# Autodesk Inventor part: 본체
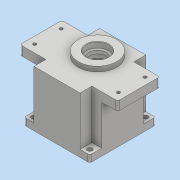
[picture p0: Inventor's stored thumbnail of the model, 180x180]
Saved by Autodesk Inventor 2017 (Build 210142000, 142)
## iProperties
Part Number: 본체
Material: 일반
Document SubType Name: Modeling
Designer: user
Density: 1 g/cm^3
Appearance: 기본값
Mass: 324.574 g
Surface Area: 793.93 cm^2
Volume: 324.574 cm^3
Author: user
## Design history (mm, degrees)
sketch "스케치1"
  geometry: L1 (0, 60)-(140, 60); L2 (140, 60)-(140, 0); L3 (140, 0)-(0, 0); L4 (0, 0)-(0, 60); L5 (37, 77)-(103, 77); L6 (103, 77)-(103, -17); L7 (103, -17)-(37, -17); L8 (37, -17)-(37, 77); 1 further point
  constraints: 16 end point, 4 parallel, 2 horizontal, 2 perpendicular, 2 point on line
  dimensions: "d0" = 140 distance of L2.end L3.end; "d1" = 60 distance of L1.end L2.end; "d2" = 66 distance of L6.end L7.end; "d3" = 94 distance of L5.end L6.end; "d4" = 17 distance between parallel lines of L1 L5; "d5" = 37 distance between parallel lines of L4 L8
extrude "돌출1" new body sketch "스케치1" distance "d6" = 13; taper "d7" = 0 deg
sketch "스케치3"
  geometry: L1 (-37, 77)-(-103, 77) reference; L2 (-37, -17)-(-103, -17); L3 (-103, -17)-(-103, 77); L4 (-103, 77)-(-37, 77); L5 (-37, 77)-(-37, -17); L6 (-37, 0)-(0, 0) reference; L7 (-23, 0)-(-117, 0); L8 (-117, 0)-(-117, 60); L9 (-117, 60)-(-23, 60); L10 (-23, 60)-(-23, 0)
  constraints: 16 end point, 4 parallel, 2 horizontal, 2 perpendicular, 1 point on line
  dimensions: "d8" = 94 distance of L8.end L9.end; "d9" = 60 distance of L7.end L8.end; "d10" = 14 distance between parallel lines of L10 L5
extrude "돌출2" join sketch "스케치3" distance "d11" = 57; taper "d12" = 0 deg
sketch "스케치4"
  geometry: L1 (-23, -17)-(-117, -17); L2 (-117, -17)-(-117, 77); L3 (-117, 77)-(-23, 77); L4 (-23, 77)-(-23, -17); 3 further points
  constraints: 8 end point, 2 parallel, 2 point on line, 1 horizontal, 1 perpendicular
  dimensions: "d13" = 94 distance of L2.end L3.end; "d14" = 94 distance of L1.end L2.end
extrude "돌출3" join sketch "스케치4" distance "d15" = 10; taper "d16" = 0 deg
sketch "스케치5"
  geometry: L1 (37, -17)-(103, -17) reference; L2 (103, 77)-(37, 77) reference; C1 r 27.5 at (70, 41); 2 further points
  constraints: 1 centre point, 1 midpoint, 1 vertical alignment
  dimensions: "d17" = 55 diameter of C1; "d18" = 58 distance from line of L1 C1.centre
extrude "돌출4" join sketch "스케치5" distance "d19" = 7; taper "d20" = 0 deg
sketch "스케치6"
  geometry: C1 r 16 at (0, 0); C2 r 27.5 at (0, 0) reference; 1 further point
  constraints: 1 centre point, 1 concentric
  dimensions: "d21" = 32 diameter of C1
extrude "돌출5" cut sketch "스케치6" distance "d22" = 8.3; taper "d23" = 0 deg
sketch "스케치7"
  geometry: C1 r 12.5 at (0, 0); C2 r 16 at (0, 0) reference; 1 further point
  constraints: 1 centre point, 1 concentric
  dimensions: "d24" = 25 diameter of C1
extrude "돌출6" cut sketch "스케치7" distance "d25" = 4.7; taper "d26" = 0 deg
sketch "스케치8"
  geometry: C1 r 17.5 at (0, 0); C2 r 12.5 at (0, 0) reference; 1 further point
  constraints: 1 centre point, 1 concentric
  dimensions: "d27" = 35 diameter of C1
sketch "스케치9"
  geometry: L1 (0, 0)-(0, 60) reference; L2 (-23, 77)-(-117, 77) reference; C1 r 43 at (-70, 30)
  constraints: 1 centre point
  dimensions: "d28" = 86 diameter of C1; "d29" = 70 distance from line of L1 C1.centre; "d30" = 47 distance from line of C1.centre L2
extrude "돌출7" cut sketch "스케치9" distance "d31" = 9; taper "d32" = 0 deg
sketch "스케치10"
  geometry: C1 r 40 at (0, 0); C2 r 43 at (0, 0) reference; 1 further point
  constraints: 1 centre point, 1 concentric
  dimensions: "d33" = 80 diameter of C1
extrude "돌출8" cut sketch "스케치10" distance "d34" = 62; taper "d35" = 0 deg
sketch "스케치11"
  geometry: C1 r 40 at (0, 0) reference; C2 r 21 at (0, 11); C3 r 15 at (0, -20); 1 further point
  constraints: 2 centre point, 2 vertical alignment
  dimensions: "d36" = 42 diameter of C2; "d37" = 30 diameter of C3; "d38" = 11 distance of C1.centre C2.centre; "d39" = 20 distance of C3.centre C1.centre
extrude "돌출9" join sketch "스케치11" distance "d40" = 7; taper "d41" = 0 deg
extrude "돌출10" cut sketch "스케치8" distance "d42" = 57; taper "d43" = 0 deg
sketch "스케치12"
  geometry: C1 r 11 at (0, -20); A1 r 15 centre (0, -20) between (-8.978, -7.984) and (8.978, -7.984) reference; 1 further point
  constraints: 1 centre point, 1 concentric
  dimensions: "d44" = 22 diameter of C1
extrude "돌출11" cut sketch "스케치12" distance "d45" = 7; taper "d46" = 0 deg
sketch "스케치13"
  geometry: C1 r 9.5 at (0, 0); C2 r 11 at (0, 0) reference; 1 further point
  constraints: 1 centre point, 1 concentric
  dimensions: "d47" = 19 diameter of C1
extrude "돌출12" cut sketch "스케치13" distance "d48" = 3; taper "d49" = 0 deg
sketch "스케치14"
  geometry: L1 (103, 77)-(37, 77) reference; L2 (23, 77)-(23, 60) reference; 2 further points
  dimensions: "d50" = 7 distance from line of L1 point (30, 70); "d51" = 7 distance from line of L2 point (30, 70)
hole "구멍1" sketch "스케치14" at (30, 70) diameter "d52" = 7; stored, may be unused: countersink angle "d56" = 90 deg, drill point angle "d58" = 118 deg; dims "d53" = 6, "d54" = 4, "d55" = 2, "d57" = 8
sketch "스케치17"
  geometry: L1 (0, 60)-(-23, 60) reference; L2 (0, 0)-(0, 60) reference; 1 further point
  dimensions: "d65" = 49 distance from line of L1 point (-10, 11); "d66" = 10 distance from line of L2 point (-10, 11)
hole "구멍2" sketch "스케치17" at (-10, 11) diameter "d67" = 4.5; stored, may be unused: countersink angle "d71" = 90 deg, drill point angle "d73" = 118 deg; dims "d68" = 6, "d69" = 10, "d70" = 5, "d72" = 8
sketch "스케치20"
  geometry: A1 r 40 centre (0, 0) between (39.279, 7.559) and (39.279, -7.559) reference; A2 r 4 centre (36, 0) between (36.19, 3.995) and (36.19, -3.995); A3 r 3 centre (36.333, 6.992) between (36.19, 3.995) and (39.279, 7.559); A4 r 3 centre (36.333, -6.992) between (39.279, -7.559) and (36.19, -3.995); 1 further point
  constraints: 8 point on circle, 4 tangent, 3 centre point, 1 horizontal alignment
  dimensions: "d86" = 8 diameter of A2; "d87" = 36 distance of A1.centre A2.centre; "d88" = 3 radius of A3; "d89" = 3 radius of A4
extrude "돌출13" join sketch "스케치20" stored distance "d90" = 3; taper "d91" = 0 deg
hole "구멍3" diameter "d94" = 3.242; stored, may be unused: countersink angle "d98" = 90 deg, drill point angle "d100" = 118 deg; dims "d92" = 10, "d93" = 10, "d95" = 7, "d96" = 10, "d97" = 5, "d99" = 9
node "작업 평면1"
sketch "스케치21"
  geometry: L1 (-14, 80)-(80, 80) reference; L2 (66, 0)-(66, 70) reference; 2 further points
  constraints: 1 other
  dimensions: "d102" = 40 distance from line of L1 point (33, 40); "d103" = 33 distance from line of L2 point (33, 40)
feature "엠보싱1" sketch "스케치21" dims "d8" = 94, "d9" = 60, "d10" = 14, "d104" = 0.5, "d105" = 0
fillet "모깎기1" dims "d106" = 3
fillet "모깎기2" dims "d107" = 3
chamfer "모따기1" distance "d108" = 1; stored, may be unused: second distance "d109" = 2, angle "d110" = 45 deg
chamfer "모따기2" distance "d111" = 0.8; stored, may be unused: second distance "d112" = 2, angle "d113" = 30 deg
fillet "모깎기3" dims "d114" = 3
chamfer "모따기3" distance "d115" = 1; stored, may be unused: second distance "d116" = 2, angle "d117" = 30 deg
chamfer "모따기4" distance "d118" = 1; stored, may be unused: second distance "d119" = 2, angle "d120" = 30 deg
node "솔리드1"
pattern_linear "직사각형 패턴1" dims "d61" = -80
pattern_linear "직사각형 패턴2" dims "d64" = 80
pattern_linear "직사각형 패턴3" dims "d76" = 38
pattern_linear "직사각형 패턴4" dims "d79" = 120
mirror "미러1"
other parameters: "d101" = -47
